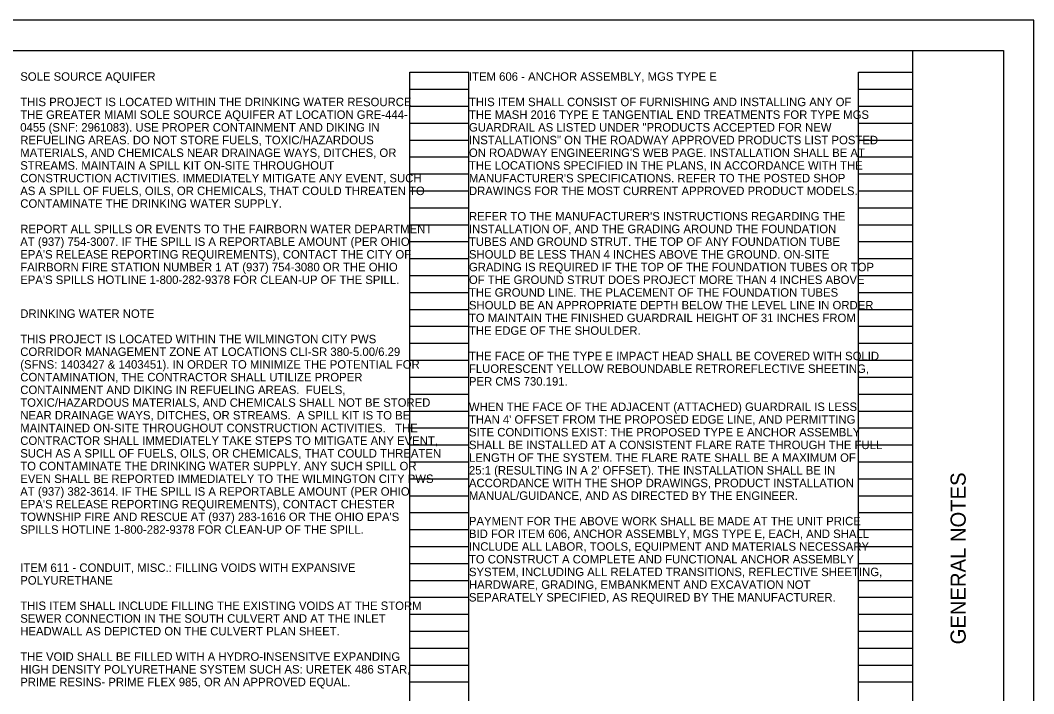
# Model space of a CAD drawing. Extents: x 0 to 34, y 0 to 22.
# Drawn here: x 17.24 to 34, y 10.87 to 22 of the extents above; entities that cross this region are included whole.
import ezdxf

# ---------------------------------------------------------------- set-up
doc = ezdxf.new("R2010")
doc.units = 0
for name, color, linetype in [('SH_Border', 7, 'Continuous'), ('SH_Cut_Line', 7, 'Continuous'), ('SH_Data', 7, 'Continuous'), ('SH_Text', 7, 'Continuous')]:
    doc.layers.add(name, color=color, linetype=linetype)

msp = doc.modelspace()

# ---------------------------------------------------------------- linework, layer by layer
at = {"layer": 'SH_Border'}
msp.add_line((32, 0.5), (32, 21.5), dxfattribs=at)
msp.add_lwpolyline([(1.5, 21.5), (33.5, 21.5), (33.5, 0.5), (1.5, 0.5)], close=True, dxfattribs=at)
at = {"layer": 'SH_Cut_Line'}
msp.add_lwpolyline([(0, 0), (34, 0), (34, 22), (0, 22)], close=True, dxfattribs=at)
at = {"layer": 'SH_Data'}
for p, q in [((23.68, 0.98), (23.68, 21.14)), ((23.68, 21.14), (24.66, 21.14)), ((24.66, 0.98), (24.66, 21.14)), ((31.1, 0.98), (31.1, 21.14)), ((31.1, 21.14), (32, 21.14)), ((32, 0.98), (32, 21.14)), ((23.68, 20.86), (24.66, 20.86)), ((31.1, 20.86), (32, 20.86)), ((23.68, 20.58), (24.66, 20.58)), ((31.1, 20.58), (32, 20.58)), ((23.68, 20.3), (24.66, 20.3)), ((31.1, 20.3), (32, 20.3)), ((23.68, 20.02), (24.66, 20.02)), ((31.1, 20.02), (32, 20.02)), ((23.68, 19.74), (24.66, 19.74)), ((31.1, 19.74), (32, 19.74)), ((23.68, 19.46), (24.66, 19.46)), ((31.1, 19.46), (32, 19.46)), ((23.68, 19.18), (24.66, 19.18)), ((31.1, 19.18), (32, 19.18)), ((23.68, 18.9), (24.66, 18.9)), ((31.1, 18.9), (32, 18.9)), ((23.68, 18.62), (24.66, 18.62)), ((31.1, 18.62), (32, 18.62)), ((23.68, 18.34), (24.66, 18.34)), ((31.1, 18.34), (32, 18.34)), ((23.68, 18.06), (24.66, 18.06)), ((31.1, 18.06), (32, 18.06)), ((23.68, 17.78), (24.66, 17.78)), ((31.1, 17.78), (32, 17.78)), ((23.68, 17.5), (24.66, 17.5)), ((31.1, 17.5), (32, 17.5)), ((23.68, 17.22), (24.66, 17.22)), ((31.1, 17.22), (32, 17.22)), ((23.68, 16.94), (24.66, 16.94)), ((31.1, 16.94), (32, 16.94)), ((23.68, 16.66), (24.66, 16.66)), ((31.1, 16.66), (32, 16.66)), ((23.68, 16.38), (24.66, 16.38)), ((31.1, 16.38), (32, 16.38)), ((23.68, 16.1), (24.66, 16.1)), ((31.1, 16.1), (32, 16.1)), ((23.68, 15.82), (24.66, 15.82)), ((31.1, 15.82), (32, 15.82)), ((23.68, 15.54), (24.66, 15.54)), ((31.1, 15.54), (32, 15.54)), ((23.68, 15.26), (24.66, 15.26)), ((31.1, 15.26), (32, 15.26)), ((23.68, 14.98), (24.66, 14.98)), ((31.1, 14.98), (32, 14.98)), ((23.68, 14.7), (24.66, 14.7)), ((31.1, 14.7), (32, 14.7)), ((23.68, 14.42), (24.66, 14.42)), ((31.1, 14.42), (32, 14.42)), ((23.68, 14.14), (24.66, 14.14)), ((31.1, 14.14), (32, 14.14)), ((23.68, 13.86), (24.66, 13.86)), ((31.1, 13.86), (32, 13.86)), ((23.68, 13.58), (24.66, 13.58)), ((31.1, 13.58), (32, 13.58)), ((23.68, 13.3), (24.66, 13.3)), ((31.1, 13.3), (32, 13.3)), ((23.68, 13.02), (24.66, 13.02)), ((31.1, 13.02), (32, 13.02)), ((23.68, 12.74), (24.66, 12.74)), ((31.1, 12.74), (32, 12.74)), ((23.68, 12.46), (24.66, 12.46)), ((31.1, 12.46), (32, 12.46)), ((23.68, 12.18), (24.66, 12.18)), ((31.1, 12.18), (32, 12.18)), ((23.68, 11.9), (24.66, 11.9)), ((31.1, 11.9), (32, 11.9)), ((23.68, 11.62), (24.66, 11.62)), ((31.1, 11.62), (32, 11.62)), ((23.68, 11.34), (24.66, 11.34)), ((31.1, 11.34), (32, 11.34)), ((23.68, 11.06), (24.66, 11.06)), ((31.1, 11.06), (32, 11.06))]:
    msp.add_line(p, q, dxfattribs=at)

# ---------------------------------------------------------------- texts
msp.add_text('GENERAL NOTES', height=0.25, rotation=90, dxfattribs=at).set_placement((32.875, 11.682))
at = {"layer": 'SH_Text'}
for s, p in [('SOLE SOURCE AQUIFER', (17.24, 21)), ('ITEM 606 - ANCHOR ASSEMBLY, MGS TYPE E', (24.66, 21)), ('THIS PROJECT IS LOCATED WITHIN THE DRINKING WATER RESOURCE ', (17.24, 20.58)), ('THIS ITEM SHALL CONSIST OF FURNISHING AND INSTALLING ANY OF ', (24.66, 20.58)), ('THE GREATER MIAMI SOLE SOURCE AQUIFER AT LOCATION GRE-444-', (17.24, 20.37)), ('THE MASH 2016 TYPE E TANGENTIAL END TREATMENTS FOR TYPE MGS ', (24.66, 20.37)), ('0455 (SNF: 2961083). USE PROPER CONTAINMENT AND DIKING IN ', (17.24, 20.16)), ('GUARDRAIL AS LISTED UNDER "PRODUCTS ACCEPTED FOR NEW ', (24.66, 20.16)), ('REFUELING AREAS. DO NOT STORE FUELS, TOXIC/HAZARDOUS ', (17.24, 19.95)), ('INSTALLATIONS" ON THE ROADWAY APPROVED PRODUCTS LIST POSTED ', (24.66, 19.95)), ('MATERIALS, AND CHEMICALS NEAR DRAINAGE WAYS, DITCHES, OR ', (17.24, 19.74)), ("ON ROADWAY ENGINEERING'S WEB PAGE. INSTALLATION SHALL BE AT ", (24.66, 19.74)), ('STREAMS. MAINTAIN A SPILL KIT ON-SITE THROUGHOUT ', (17.24, 19.53)), ('THE LOCATIONS SPECIFIED IN THE PLANS, IN ACCORDANCE WITH THE ', (24.66, 19.53)), ('CONSTRUCTION ACTIVITIES. IMMEDIATELY MITIGATE ANY EVENT, SUCH ', (17.24, 19.32)), ("MANUFACTURER'S SPECIFICATIONS. REFER TO THE POSTED SHOP ", (24.66, 19.32)), ('AS A SPILL OF FUELS, OILS, OR CHEMICALS, THAT COULD THREATEN TO ', (17.24, 19.11)), ('DRAWINGS FOR THE MOST CURRENT APPROVED PRODUCT MODELS.', (24.66, 19.11)), ('CONTAMINATE THE DRINKING WATER SUPPLY. ', (17.24, 18.9)), ("REFER TO THE MANUFACTURER'S INSTRUCTIONS REGARDING THE ", (24.66, 18.69)), ('REPORT ALL SPILLS OR EVENTS TO THE FAIRBORN WATER DEPARTMENT ', (17.24, 18.48)), ('INSTALLATION OF, AND THE GRADING AROUND THE FOUNDATION ', (24.66, 18.48)), ('AT (937) 754-3007. IF THE SPILL IS A REPORTABLE AMOUNT (PER OHIO ', (17.24, 18.27)), ('TUBES AND GROUND STRUT. THE TOP OF ANY FOUNDATION TUBE ', (24.66, 18.27)), ("EPA'S RELEASE REPORTING REQUIREMENTS), CONTACT THE CITY OF ", (17.24, 18.06)), ('SHOULD BE LESS THAN 4 INCHES ABOVE THE GROUND. ON-SITE ', (24.66, 18.06)), ('FAIRBORN FIRE STATION NUMBER 1 AT (937) 754-3080 OR THE OHIO ', (17.24, 17.85)), ('GRADING IS REQUIRED IF THE TOP OF THE FOUNDATION TUBES OR TOP ', (24.66, 17.85)), ("EPA'S SPILLS HOTLINE 1-800-282-9378 FOR CLEAN-UP OF THE SPILL.", (17.24, 17.64)), ('OF THE GROUND STRUT DOES PROJECT MORE THAN 4 INCHES ABOVE ', (24.66, 17.64)), ('THE GROUND LINE. THE PLACEMENT OF THE FOUNDATION TUBES ', (24.66, 17.43)), ('SHOULD BE AN APPROPRIATE DEPTH BELOW THE LEVEL LINE IN ORDER ', (24.66, 17.22)), ('DRINKING WATER NOTE', (17.24, 17.08)), ('TO MAINTAIN THE FINISHED GUARDRAIL HEIGHT OF 31 INCHES FROM ', (24.66, 17.01)), ('THE EDGE OF THE SHOULDER.', (24.66, 16.8)), ('THIS PROJECT IS LOCATED WITHIN THE WILMINGTON CITY PWS ', (17.24, 16.66)), ('CORRIDOR MANAGEMENT ZONE AT LOCATIONS CLI-SR 380-5.00/6.29 ', (17.24, 16.45)), ('THE FACE OF THE TYPE E IMPACT HEAD SHALL BE COVERED WITH SOLID ', (24.66, 16.38)), ('(SFNS: 1403427 & 1403451). IN ORDER TO MINIMIZE THE POTENTIAL FOR ', (17.24, 16.24)), ('FLUORESCENT YELLOW REBOUNDABLE RETROREFLECTIVE SHEETING, ', (24.66, 16.17)), ('CONTAMINATION, THE CONTRACTOR SHALL UTILIZE PROPER ', (17.24, 16.03)), ('PER CMS 730.191.', (24.66, 15.96)), ('CONTAINMENT AND DIKING IN REFUELING AREAS.  FUELS, ', (17.24, 15.82)), ('TOXIC/HAZARDOUS MATERIALS, AND CHEMICALS SHALL NOT BE STORED ', (17.24, 15.61)), ('WHEN THE FACE OF THE ADJACENT (ATTACHED) GUARDRAIL IS LESS ', (24.66, 15.54)), ('NEAR DRAINAGE WAYS, DITCHES, OR STREAMS.  A SPILL KIT IS TO BE ', (17.24, 15.4)), ("THAN 4' OFFSET FROM THE PROPOSED EDGE LINE, AND PERMITTING ", (24.66, 15.33)), ('MAINTAINED ON-SITE THROUGHOUT CONSTRUCTION ACTIVITIES.   THE ', (17.24, 15.19)), ('SITE CONDITIONS EXIST: THE PROPOSED TYPE E ANCHOR ASSEMBLY ', (24.66, 15.12)), ('CONTRACTOR SHALL IMMEDIATELY TAKE STEPS TO MITIGATE ANY EVENT, ', (17.24, 14.98)), ('SHALL BE INSTALLED AT A CONSISTENT FLARE RATE THROUGH THE FULL ', (24.66, 14.91)), ('SUCH AS A SPILL OF FUELS, OILS, OR CHEMICALS, THAT COULD THREATEN ', (17.24, 14.77)), ('LENGTH OF THE SYSTEM. THE FLARE RATE SHALL BE A MAXIMUM OF ', (24.66, 14.7)), ('TO CONTAMINATE THE DRINKING WATER SUPPLY. ANY SUCH SPILL OR ', (17.24, 14.56)), ("25:1 (RESULTING IN A 2' OFFSET). THE INSTALLATION SHALL BE IN ", (24.66, 14.49)), ('EVEN SHALL BE REPORTED IMMEDIATELY TO THE WILMINGTON CITY PWS ', (17.24, 14.35)), ('ACCORDANCE WITH THE SHOP DRAWINGS, PRODUCT INSTALLATION ', (24.66, 14.28)), ('AT (937) 382-3614. IF THE SPILL IS A REPORTABLE AMOUNT (PER OHIO ', (17.24, 14.14)), ('MANUAL/GUIDANCE, AND AS DIRECTED BY THE ENGINEER. ', (24.66, 14.07)), ("EPA'S RELEASE REPORTING REQUIREMENTS), CONTACT CHESTER ", (17.24, 13.93)), ("TOWNSHIP FIRE AND RESCUE AT (937) 283-1616 OR THE OHIO EPA'S ", (17.24, 13.72)), ('PAYMENT FOR THE ABOVE WORK SHALL BE MADE AT THE UNIT PRICE ', (24.66, 13.65)), ('SPILLS HOTLINE 1-800-282-9378 FOR CLEAN-UP OF THE SPILL.', (17.24, 13.51)), ('BID FOR ITEM 606, ANCHOR ASSEMBLY, MGS TYPE E, EACH, AND SHALL ', (24.66, 13.44)), ('INCLUDE ALL LABOR, TOOLS, EQUIPMENT AND MATERIALS NECESSARY ', (24.66, 13.23)), ('TO CONSTRUCT A COMPLETE AND FUNCTIONAL ANCHOR ASSEMBLY ', (24.66, 13.02)), ('ITEM 611 - CONDUIT, MISC.: FILLING VOIDS WITH EXPANSIVE ', (17.24, 12.88)), ('SYSTEM, INCLUDING ALL RELATED TRANSITIONS, REFLECTIVE SHEETING, ', (24.66, 12.81)), ('POLYURETHANE', (17.24, 12.67)), ('HARDWARE, GRADING, EMBANKMENT AND EXCAVATION NOT ', (24.66, 12.6)), ('SEPARATELY SPECIFIED, AS REQUIRED BY THE MANUFACTURER.', (24.66, 12.39)), ('THIS ITEM SHALL INCLUDE FILLING THE EXISTING VOIDS AT THE STORM ', (17.24, 12.25)), ('SEWER CONNECTION IN THE SOUTH CULVERT AND AT THE INLET ', (17.24, 12.04)), ('HEADWALL AS DEPICTED ON THE CULVERT PLAN SHEET.', (17.24, 11.83)), ('THE VOID SHALL BE FILLED WITH A HYDRO-INSENSITVE EXPANDING ', (17.24, 11.41)), ('HIGH DENSITY POLYURETHANE SYSTEM SUCH AS: URETEK 486 STAR, ', (17.24, 11.2)), ('PRIME RESINS- PRIME FLEX 985, OR AN APPROVED EQUAL.', (17.24, 10.99))]:
    msp.add_text(s, height=0.14, dxfattribs=at).set_placement(p)

doc.saveas('drawing.dxf')
